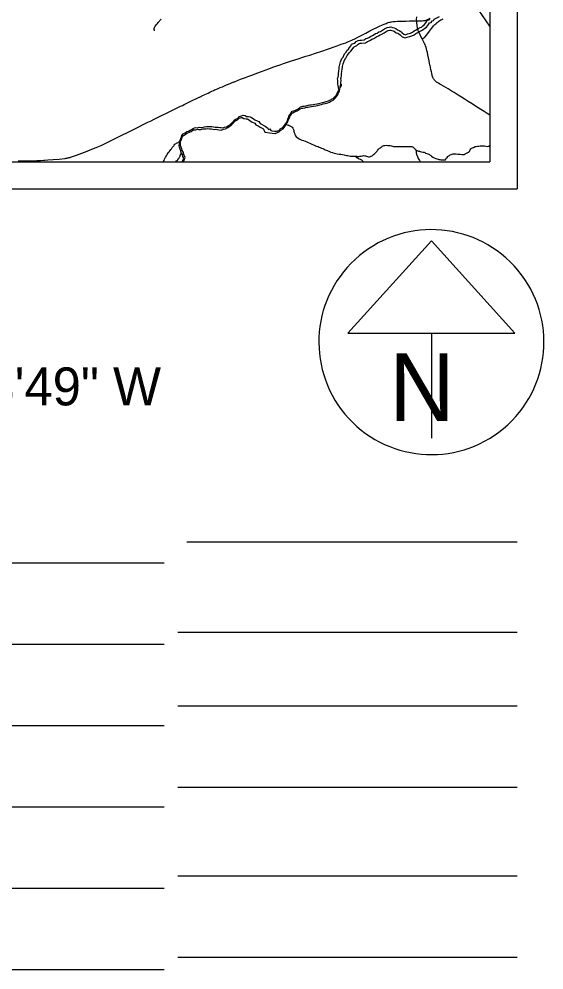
# Model space of a CAD drawing. Extents: x 0 to 34, y -1.2 to 22.
# Drawn here: x 7.165 to 9.099, y 11.12 to 14.627 of the extents above; entities that cross this region are included whole.
import ezdxf

# ---------------------------------------------------------------- set-up
doc = ezdxf.new("R2010")
doc.units = 0
for name, color, linetype in [('GM_X_City_Street', 7, 'Continuous'), ('GM_X_County_Road', 7, 'Continuous'), ('GM_X_Rail_Line', 7, 'Continuous'), ('SH_Cut_Line', 7, 'Continuous'), ('SH_Data', 7, 'Continuous')]:
    doc.layers.add(name, color=color, linetype=linetype)

msp = doc.modelspace()

# ---------------------------------------------------------------- linework, layer by layer
at = {"layer": 'GM_X_City_Street'}
for points in [[(7.6644, 14.5829), (7.6638, 14.5844), (7.6636, 14.5852), (7.6634, 14.586), (7.6632, 14.5867), (7.6631, 14.5875), (7.663, 14.5883), (7.6632, 14.5923), (7.6633, 14.5931), (7.6635, 14.5938), (7.6638, 14.5948), (7.6641, 14.5957), (7.6645, 14.5966), (7.6649, 14.5975), (7.6654, 14.5984), (7.6659, 14.5992), (7.6664, 14.6), (7.6673, 14.6012), (7.6681, 14.6022), (7.6714, 14.6063), (7.6747, 14.6104), (7.678, 14.6145), (7.6882, 14.6268)], [(8.6302, 14.6201), (8.6382, 14.62), (8.6454, 14.6201), (8.651, 14.6204), (8.6559, 14.6208), (8.6603, 14.6215), (8.6628, 14.6219), (8.6651, 14.6226), (8.6676, 14.6235), (8.67, 14.6246), (8.6723, 14.6258), (8.6746, 14.6271)], [(8.6506, 14.5537), (8.6569, 14.557), (8.6593, 14.5587), (8.6615, 14.561), (8.6665, 14.5671), (8.6716, 14.5739), (8.6778, 14.5822), (8.6854, 14.5918), (8.6902, 14.5982), (8.6925, 14.6012), (8.695, 14.604), (8.6975, 14.6067), (8.7002, 14.6094), (8.703, 14.6119), (8.7058, 14.6143), (8.7088, 14.6165), (8.7118, 14.6188), (8.7155, 14.6211), (8.7192, 14.6233), (8.723, 14.6254), (8.7279, 14.628)]]:
    msp.add_lwpolyline(points, dxfattribs=at)
at = {"layer": 'GM_X_County_Road'}
for points in [[(8.6793, 14.4567), (8.678, 14.4635), (8.6762, 14.4731), (8.6741, 14.4838), (8.6718, 14.4948), (8.6698, 14.5036), (8.6682, 14.5103), (8.6669, 14.5155), (8.6649, 14.5223), (8.6626, 14.5284), (8.6609, 14.5328), (8.6591, 14.5369), (8.6567, 14.5419), (8.6506, 14.5537), (8.6461, 14.5627), (8.6413, 14.572), (8.639, 14.577), (8.6375, 14.5805), (8.6357, 14.5859), (8.6346, 14.5899), (8.6333, 14.5952), (8.6324, 14.5999), (8.6317, 14.6043), (8.6307, 14.6122), (8.6304, 14.6158), (8.6302, 14.6201), (8.6301, 14.6249), (8.6304, 14.6344)], [(8.3522, 14.5335), (8.3687, 14.5395), (8.3794, 14.5438), (8.3911, 14.5489), (8.4046, 14.5552), (8.4138, 14.5598), (8.4236, 14.5649), (8.4431, 14.5751), (8.4578, 14.5829), (8.4719, 14.5902), (8.4812, 14.5947), (8.4928, 14.6001), (8.5043, 14.6053), (8.5109, 14.6081), (8.5176, 14.6108), (8.521, 14.6121), (8.5252, 14.6134), (8.53, 14.6147), (8.5337, 14.6156), (8.5378, 14.6164), (8.5438, 14.6171), (8.5511, 14.6177), (8.5597, 14.6183), (8.5734, 14.6188), (8.591, 14.6193), (8.6036, 14.6197), (8.6178, 14.6199), (8.6302, 14.6201)], [(7.1616, 14.1042), (7.1742, 14.1038), (7.2076, 14.104), (7.2191, 14.1042), (7.2302, 14.1046), (7.2443, 14.1052), (7.2558, 14.1058), (7.2593, 14.1059), (7.2703, 14.107), (7.2909, 14.1087), (7.3125, 14.1105), (7.3331, 14.1127), (7.3353, 14.113), (7.3375, 14.1133), (7.3397, 14.1137), (7.3419, 14.1141), (7.3441, 14.1145), (7.3463, 14.115), (7.3484, 14.1155), (7.3506, 14.1161), (7.3527, 14.1167), (7.3548, 14.1173), (7.3761, 14.1248), (7.396, 14.1325), (7.4159, 14.1399), (7.4334, 14.1467), (7.4493, 14.1529), (7.4674, 14.1609), (7.482, 14.1676), (7.4849, 14.1689), (7.502, 14.1771), (7.5215, 14.1868), (7.5387, 14.1954), (7.5723, 14.2122), (7.5896, 14.2208), (7.6063, 14.2292), (7.6226, 14.2374), (7.6398, 14.2459), (7.6514, 14.2519), (7.6625, 14.2575), (7.6754, 14.2639), (7.69, 14.2711), (7.7038, 14.2777), (7.7135, 14.2824), (7.7231, 14.2871), (7.7352, 14.2929), (7.7449, 14.2977), (7.75, 14.3001), (7.7548, 14.3025), (7.7596, 14.3049), (7.7668, 14.3083), (7.7739, 14.3118), (7.7811, 14.3152), (7.8004, 14.3246), (7.8217, 14.3348), (7.8259, 14.3369), (7.8301, 14.339), (7.8343, 14.341), (7.8386, 14.3431), (7.849, 14.3479), (7.8551, 14.3508), (7.8613, 14.3537), (7.8673, 14.3567), (7.8748, 14.3603), (7.8809, 14.3631), (7.8855, 14.3652), (7.8901, 14.3672), (7.898, 14.3706), (7.906, 14.3739), (7.914, 14.3772), (7.9216, 14.3805), (7.9292, 14.3837), (7.9369, 14.3868), (7.9558, 14.3946), (7.9584, 14.3957), (7.9815, 14.4045), (7.9887, 14.4071), (7.999, 14.4112), (8.0121, 14.416), (8.0258, 14.421), (8.0412, 14.4268), (8.0578, 14.433), (8.0724, 14.4384), (8.0853, 14.4433), (8.1006, 14.449), (8.1146, 14.4538), (8.1271, 14.4584), (8.1396, 14.4626), (8.1543, 14.4671), (8.1692, 14.4722), (8.1813, 14.4761), (8.1929, 14.4799), (8.2141, 14.4868), (8.2221, 14.4893), (8.2363, 14.4938), (8.257, 14.5007), (8.2804, 14.5084), (8.3015, 14.5156), (8.334, 14.5271), (8.3522, 14.5335)], [(8.9, 14.2721), (8.8901, 14.2786), (8.8791, 14.2855), (8.867, 14.2931), (8.8573, 14.2992), (8.8469, 14.3059), (8.8343, 14.3139), (8.8201, 14.3229), (8.8053, 14.3323), (8.7955, 14.3386), (8.7832, 14.3463), (8.7684, 14.3556), (8.7613, 14.36), (8.7458, 14.3695), (8.7375, 14.3744), (8.729, 14.3793), (8.7204, 14.3841), (8.7152, 14.3871), (8.7102, 14.3899), (8.7077, 14.3914), (8.7052, 14.3929), (8.7033, 14.3941), (8.7015, 14.3955), (8.6998, 14.397), (8.6983, 14.3986), (8.6959, 14.4016), (8.6943, 14.4038), (8.6928, 14.4061), (8.6915, 14.4085), (8.6902, 14.4114), (8.6889, 14.4152), (8.6876, 14.419), (8.6857, 14.4265), (8.6843, 14.432), (8.6825, 14.4408), (8.681, 14.4482), (8.6795, 14.4557), (8.6793, 14.4567)]]:
    msp.add_lwpolyline(points, dxfattribs=at)
at = {"layer": 'GM_X_Rail_Line'}
msp.add_lwpolyline([(8.9, 14.6003), (8.7511, 14.8178), (8.2939, 15.4393), (8.2013, 15.551), (8.1077, 15.6378), (7.701, 15.9652), (6.7828, 16.6979), (6.6486, 16.8082), (6.5509, 16.8914), (6.4799, 16.9767), (6.4285, 17.0577), (6.3663, 17.169), (6.2482, 17.4528), (6.016, 18.0566), (5.7261, 18.7395), (5.6762, 18.8315), (5.6316, 18.8789), (5.6274, 18.8834)], dxfattribs=at)
at = {"layer": 'SH_Data'}
for p, q in [((9, 21), (9, 14)), ((8.9, 20.9), (8.9, 14.1)), ((2.1, 14.1), (8.9, 14.1)), ((2, 14), (9, 14)), ((8.6845, 13.8091), (8.3769, 13.4678)), ((8.9921, 13.4678), (8.6845, 13.8091)), ((8.3769, 13.4678), (8.9921, 13.4678)), ((8.6845, 13.4678), (8.6845, 13.0811)), ((8.6845, 13.4353), (8.6845, 13.4353)), ((8.6845, 13.4353), (8.6845, 13.4353)), ((7.7827, 12.6985), (9, 12.6985)), ((7.7, 12.6199), (4.4937, 12.6199)), ((9, 12.3639), (7.75, 12.3639)), ((7.7, 12.3199), (3.9895, 12.3199)), ((9, 12.0923), (7.75, 12.0923)), ((7.7, 12.0199), (3.6192, 12.0199)), ((9, 11.7923), (7.75, 11.7923)), ((7.7, 11.7199), (3.3288, 11.7199)), ((9, 11.4655), (7.75, 11.4655)), ((7.7, 11.4199), (4.7452, 11.4199)), ((9, 11.1655), (7.75, 11.1655)), ((7.7, 11.1199), (3.3471, 11.1199))]:
    msp.add_line(p, q, dxfattribs=at)
for points in [[(8.3413, 14.3813), (8.3401, 14.3864), (8.3396, 14.3918), (8.34, 14.4005), (8.3388, 14.4069), (8.3406, 14.4126), (8.3417, 14.4187), (8.3421, 14.4252), (8.3435, 14.4358), (8.3446, 14.443), (8.345, 14.4491), (8.3461, 14.4544), (8.3479, 14.4639), (8.3494, 14.4692), (8.352, 14.4753), (8.3542, 14.481), (8.3587, 14.486), (8.3613, 14.4917), (8.3647, 14.4986), (8.37, 14.505), (8.3733, 14.5104), (8.3786, 14.5153), (8.3831, 14.5214), (8.3888, 14.5287), (8.3906, 14.5336), (8.3974, 14.5359), (8.4023, 14.5382), (8.4076, 14.544), (8.414, 14.547), (8.4208, 14.549), (8.4265, 14.549), (8.4371, 14.5498), (8.4431, 14.5544), (8.4484, 14.5563), (8.4541, 14.5586), (8.4598, 14.5625), (8.4669, 14.5656), (8.4733, 14.5698), (8.479, 14.5728), (8.4843, 14.5748), (8.4903, 14.579), (8.4964, 14.5809), (8.5043, 14.5859), (8.5115, 14.5905), (8.5164, 14.5932), (8.522, 14.5955), (8.5292, 14.597), (8.5353, 14.5974), (8.5417, 14.596), (8.5474, 14.5945), (8.5535, 14.5915), (8.56, 14.5866), (8.5661, 14.5847), (8.5718, 14.5806), (8.5767, 14.5764), (8.5824, 14.5711), (8.5885, 14.5689), (8.5961, 14.5716), (8.6021, 14.5728), (8.6078, 14.5747), (8.6146, 14.5785), (8.6206, 14.5827), (8.6263, 14.5858), (8.6323, 14.5896), (8.638, 14.5927), (8.6433, 14.595), (8.6482, 14.5973), (8.6531, 14.6015), (8.658, 14.605), (8.6644, 14.613), (8.6707, 14.6225), (8.6764, 14.624), (8.6802, 14.6298)], [(8.3484, 14.3751), (8.3513, 14.3882), (8.351, 14.392), (8.3514, 14.4013), (8.3505, 14.4061), (8.3517, 14.4099), (8.3531, 14.4174), (8.3534, 14.4241), (8.3548, 14.4342), (8.3559, 14.4419), (8.3563, 14.4476), (8.3572, 14.4522), (8.359, 14.4613), (8.3601, 14.4655), (8.3625, 14.471), (8.364, 14.4749), (8.3683, 14.4796), (8.3716, 14.4868), (8.3743, 14.4924), (8.3792, 14.4984), (8.3822, 14.5031), (8.3872, 14.5078), (8.3922, 14.5146), (8.3988, 14.5231), (8.3994, 14.5246), (8.4017, 14.5254), (8.4092, 14.5289), (8.4145, 14.5346), (8.4181, 14.5364), (8.4224, 14.5376), (8.427, 14.5376), (8.4413, 14.5387), (8.4486, 14.5443), (8.4525, 14.5457), (8.4595, 14.5486), (8.4652, 14.5525), (8.4723, 14.5555), (8.4792, 14.56), (8.4837, 14.5624), (8.4896, 14.5646), (8.4954, 14.5687), (8.5012, 14.5705), (8.5104, 14.5763), (8.5173, 14.5807), (8.5213, 14.5829), (8.5254, 14.5846), (8.5308, 14.5857), (8.5344, 14.586), (8.539, 14.5849), (8.5434, 14.5838), (8.5475, 14.5818), (8.5547, 14.5763), (8.5609, 14.5744), (8.5648, 14.5716), (8.5692, 14.5679), (8.5764, 14.5613), (8.5884, 14.5568), (8.5991, 14.5606), (8.605, 14.5618), (8.6125, 14.5643), (8.6206, 14.5689), (8.6266, 14.573), (8.632, 14.576), (8.6381, 14.5798), (8.643, 14.5825), (8.648, 14.5847), (8.6544, 14.5877), (8.6601, 14.5925), (8.6658, 14.5966), (8.6735, 14.6063), (8.6778, 14.6126), (8.6835, 14.6142), (8.6874, 14.6201), (8.6926, 14.6218), (8.6952, 14.626), (8.7142, 14.6355)], [(8.0278, 14.2593), (8.0343, 14.2544), (8.0427, 14.2514), (8.0487, 14.2488), (8.053, 14.2419), (8.0587, 14.2393), (8.0663, 14.2344), (8.0716, 14.2322), (8.0765, 14.2284), (8.0819, 14.2246), (8.0842, 14.2197), (8.0894, 14.2213), (8.0921, 14.2156), (8.0978, 14.2149), (8.1058, 14.2134), (8.1141, 14.2127), (8.119, 14.215), (8.1243, 14.2173), (8.1273, 14.2222), (8.1322, 14.2242), (8.1375, 14.2272), (8.1428, 14.2337), (8.1458, 14.2398), (8.1514, 14.2467), (8.1536, 14.2531), (8.1559, 14.2585), (8.1589, 14.2638), (8.1588, 14.2687), (8.1641, 14.2752), (8.1675, 14.2809), (8.1716, 14.2866), (8.1769, 14.2886), (8.1833, 14.2909), (8.1913, 14.2943), (8.1977, 14.2986), (8.2026, 14.3024), (8.2109, 14.3051), (8.2158, 14.3059), (8.2222, 14.307), (8.2306, 14.3094), (8.2362, 14.3098), (8.2412, 14.3106), (8.2483, 14.3114), (8.2548, 14.3129), (8.2635, 14.3141), (8.2688, 14.3153), (8.2778, 14.3176), (8.2835, 14.3188), (8.2896, 14.3207), (8.2964, 14.3226), (8.3058, 14.3254), (8.3107, 14.3273), (8.3183, 14.3319), (8.3232, 14.3338), (8.3285, 14.3395), (8.333, 14.3445), (8.3371, 14.3506), (8.3386, 14.3559), (8.3416, 14.3609), (8.3431, 14.3677), (8.3413, 14.3815)], [(8.3516, 14.3871), (8.3518, 14.381), (8.3484, 14.3751)], [(8.0139, 14.2537), (8.0218, 14.2478), (8.0314, 14.2443), (8.0339, 14.2433), (8.038, 14.2366), (8.0461, 14.2329), (8.0539, 14.2279), (8.0588, 14.2258), (8.0627, 14.2228), (8.0658, 14.2206), (8.071, 14.2095), (8.089, 14.2072), (8.0972, 14.2057), (8.1091, 14.2046), (8.1167, 14.2082), (8.1251, 14.2119), (8.128, 14.2166), (8.1301, 14.2174), (8.138, 14.222), (8.1453, 14.2311), (8.1483, 14.2372), (8.1544, 14.2446), (8.1572, 14.2526), (8.159, 14.257), (8.1632, 14.2644), (8.1632, 14.2683), (8.1664, 14.2722), (8.1699, 14.2782), (8.1717, 14.2807), (8.1737, 14.2814), (8.1805, 14.2839), (8.1896, 14.2878), (8.1972, 14.2928), (8.2009, 14.2957), (8.2065, 14.2975), (8.2107, 14.2982), (8.2177, 14.2995), (8.2254, 14.3017), (8.2305, 14.302), (8.2356, 14.3028), (8.2432, 14.3037), (8.2498, 14.3053), (8.2584, 14.3064), (8.2643, 14.3078), (8.2733, 14.3101), (8.2793, 14.3113), (8.2858, 14.3134), (8.2924, 14.3153), (8.3024, 14.3181), (8.3087, 14.3206), (8.3163, 14.3252), (8.3227, 14.3277), (8.3298, 14.3354), (8.3349, 14.341), (8.3405, 14.3493), (8.3421, 14.3549), (8.3452, 14.3601), (8.3484, 14.3751)], [(7.7669, 14.1), (7.7671, 14.1003), (7.769, 14.106), (7.7716, 14.1132), (7.7681, 14.1193), (7.7673, 14.1272), (7.7627, 14.1333), (7.7612, 14.1409), (7.7585, 14.1465), (7.7558, 14.1537), (7.7554, 14.1587), (7.7557, 14.1651), (7.7561, 14.1708), (7.7556, 14.1757), (7.7594, 14.1822), (7.7609, 14.1875), (7.7631, 14.1925), (7.765, 14.1974), (7.7702, 14.2028), (7.7774, 14.2074), (7.7834, 14.2116), (7.7891, 14.2135), (7.7952, 14.217), (7.8004, 14.2189), (7.8065, 14.2231), (7.8118, 14.2254), (7.8167, 14.2262), (7.822, 14.2258), (7.8292, 14.2282), (7.8349, 14.2271), (7.8402, 14.2271), (7.8481, 14.229), (7.8553, 14.2302), (7.8614, 14.2302), (7.8678, 14.2307), (7.875, 14.2299), (7.8811, 14.2292), (7.8871, 14.2285), (7.8924, 14.2278), (7.8981, 14.2278), (7.9046, 14.2267), (7.9099, 14.2263), (7.9152, 14.2256), (7.9216, 14.2279), (7.9288, 14.2295), (7.9352, 14.2329), (7.9424, 14.2379), (7.948, 14.2421), (7.9533, 14.2478), (7.9601, 14.2555), (7.9653, 14.2582), (7.9706, 14.2605), (7.9778, 14.2673), (7.9842, 14.2693), (7.9906, 14.272), (7.9978, 14.2705), (8.0035, 14.2675), (8.01, 14.2668), (8.016, 14.2664), (8.0214, 14.2638), (8.0278, 14.2593)], [(7.7708, 14.1), (7.7727, 14.1058), (7.777, 14.1178), (7.7721, 14.1263), (7.7712, 14.1351), (7.7663, 14.1416), (7.765, 14.148), (7.7619, 14.1545), (7.7599, 14.1598), (7.7597, 14.1624), (7.76, 14.168), (7.7604, 14.1745), (7.7602, 14.1767), (7.7629, 14.1813), (7.7645, 14.1872), (7.7666, 14.1917), (7.7677, 14.1947), (7.7704, 14.1974), (7.7767, 14.2015), (7.7816, 14.2049), (7.7867, 14.2066), (7.7929, 14.2101), (7.7987, 14.2123), (7.805, 14.2167), (7.8079, 14.2179), (7.8101, 14.2183), (7.8163, 14.2179), (7.8228, 14.22), (7.8267, 14.2192), (7.8345, 14.2193), (7.8433, 14.2214), (7.8492, 14.2224), (7.8547, 14.2224), (7.8605, 14.2228), (7.8667, 14.2222), (7.8726, 14.2215), (7.8786, 14.2207), (7.8846, 14.2199), (7.8901, 14.22), (7.8962, 14.2189), (7.9016, 14.2186), (7.9093, 14.2175), (7.9177, 14.2205), (7.9257, 14.2222), (7.9341, 14.2268), (7.9419, 14.2322), (7.9486, 14.2372), (7.9547, 14.2438), (7.9601, 14.2498), (7.9631, 14.2514), (7.97, 14.2544), (7.9766, 14.2608), (7.981, 14.2621), (7.9847, 14.2637), (7.9869, 14.2632), (7.9931, 14.26), (8.002, 14.259), (8.006, 14.2587), (8.0085, 14.2575), (8.0143, 14.2535)], [(8.1487, 14.2376), (8.1606, 14.2338), (8.1572, 14.2349), (8.1606, 14.2338), (8.1633, 14.2331), (8.1652, 14.232), (8.1671, 14.2305), (8.1694, 14.2294), (8.1714, 14.2275), (8.1733, 14.2245), (8.1752, 14.2219), (8.1768, 14.2196), (8.1776, 14.2162), (8.178, 14.2124), (8.1788, 14.2086), (8.1796, 14.2056), (8.1808, 14.2029), (8.1816, 14.2003), (8.1827, 14.198), (8.1839, 14.1961), (8.1859, 14.1927), (8.1889, 14.1905), (8.1973, 14.1845), (8.2015, 14.1823), (8.2073, 14.1801), (8.2134, 14.1782), (8.2195, 14.1764), (8.2252, 14.1742), (8.2309, 14.1716), (8.2366, 14.1686), (8.2439, 14.1657), (8.2496, 14.1631), (8.2553, 14.1601), (8.2603, 14.1583), (8.2645, 14.1572), (8.2675, 14.1561), (8.2706, 14.1546), (8.2744, 14.1528), (8.279, 14.1505), (8.2843, 14.1487), (8.2893, 14.1473), (8.2931, 14.1446), (8.3, 14.1421), (8.3065, 14.1391), (8.3133, 14.1361), (8.3202, 14.134), (8.3263, 14.1321), (8.332, 14.1307), (8.3377, 14.13), (8.3445, 14.1289), (8.3506, 14.1279), (8.3571, 14.1268), (8.3632, 14.1258), (8.3712, 14.124), (8.3769, 14.1229), (8.3818, 14.1218), (8.386, 14.1211), (8.3902, 14.1204), (8.3951, 14.1205), (8.4001, 14.1205), (8.4054, 14.1206), (8.4092, 14.1206), (8.4115, 14.1203), (8.4137, 14.1199), (8.4168, 14.12), (8.4202, 14.1204), (8.4228, 14.1208), (8.4259, 14.1212), (8.43, 14.1224), (8.4346, 14.1229), (8.4387, 14.1225), (8.4418, 14.1222), (8.4528, 14.1185), (8.4563, 14.1186), (8.46, 14.1194), (8.4627, 14.1209), (8.4657, 14.1225), (8.4683, 14.1244), (8.4713, 14.1268), (8.4751, 14.1298), (8.4785, 14.1329), (8.4815, 14.136), (8.4841, 14.1391), (8.4863, 14.1422), (8.4893, 14.1464), (8.493, 14.1502), (8.4964, 14.1522), (8.499, 14.1545), (8.5013, 14.156), (8.5036, 14.1576), (8.5062, 14.1591), (8.5096, 14.1599), (8.5134, 14.1608), (8.5187, 14.1612), (8.5236, 14.1609), (8.5282, 14.1602), (8.5328, 14.1599), (8.5373, 14.1588), (8.5408, 14.1577), (8.5449, 14.157), (8.5487, 14.1563)], [(7.6972, 14.1), (7.6975, 14.1009), (7.699, 14.1051), (7.7012, 14.1105), (7.7049, 14.1174), (7.7078, 14.1227), (7.7108, 14.1277), (7.7145, 14.1331), (7.7183, 14.1373), (7.7213, 14.1419), (7.7242, 14.1457), (7.7269, 14.1484), (7.7295, 14.153), (7.7324, 14.1565), (7.7347, 14.1596), (7.7369, 14.1619), (7.7392, 14.1653), (7.7557, 14.1756)], [(8.5487, 14.1563), (8.5525, 14.1563), (8.5582, 14.1564), (8.5647, 14.1565), (8.5715, 14.1562), (8.5768, 14.1562), (8.581, 14.1567), (8.5848, 14.1563), (8.5886, 14.1568), (8.5946, 14.1569), (8.5996, 14.1569), (8.6038, 14.157), (8.6079, 14.157), (8.6121, 14.1563), (8.6152, 14.1552), (8.6178, 14.1537), (8.6198, 14.1519), (8.6221, 14.1496), (8.6244, 14.147), (8.6267, 14.1447), (8.6301, 14.1421), (8.632, 14.1414), (8.6374, 14.1399), (8.64, 14.1396), (8.6435, 14.1385), (8.648, 14.137), (8.653, 14.1363), (8.6572, 14.1352), (8.6598, 14.1341), (8.6629, 14.1322), (8.6682, 14.1308), (8.6717, 14.1297), (8.6751, 14.1282), (8.6778, 14.1267), (8.6801, 14.1252), (8.6824, 14.123), (8.6854, 14.1207), (8.6897, 14.1178), (8.695, 14.1148), (8.7003, 14.1126), (8.7049, 14.1115), (8.7095, 14.11), (8.7122, 14.1093), (8.7156, 14.1086), (8.7198, 14.1079), (8.7239, 14.1075), (8.7274, 14.1076), (8.7304, 14.1076), (8.7338, 14.1077), (8.7365, 14.1081), (8.739, 14.1131), (8.7424, 14.1165), (8.7447, 14.1192), (8.7465, 14.1204), (8.7484, 14.1223), (8.751, 14.1239), (8.7541, 14.1258), (8.7575, 14.127), (8.7609, 14.1285), (8.765, 14.1297), (8.7673, 14.1298), (8.7692, 14.1298), (8.7719, 14.1295), (8.776, 14.1291), (8.7825, 14.1284), (8.7901, 14.1278), (8.7965, 14.1275), (8.8049, 14.1272), (8.8083, 14.1295), (8.8143, 14.1319), (8.8188, 14.1342), (8.8222, 14.1358), (8.8241, 14.1377), (8.8256, 14.1396), (8.8263, 14.1416), (8.8278, 14.1446), (8.8297, 14.1477), (8.8327, 14.15), (8.8361, 14.1519), (8.8395, 14.1535), (8.8455, 14.1563), (8.8497, 14.1571), (8.8538, 14.1579), (8.8588, 14.1583), (8.8641, 14.1588), (8.8694, 14.1588), (8.8743, 14.1589), (8.8796, 14.1586), (8.8853, 14.1579), (8.8903, 14.1572), (8.8941, 14.1573), (8.8963, 14.1584), (8.8993, 14.16), (8.9, 14.161)], [(8.6273, 14.1443), (8.6296, 14.1257), (8.6315, 14.1235), (8.6331, 14.1197), (8.6343, 14.1167), (8.6362, 14.1125), (8.6382, 14.1087), (8.6405, 14.1053), (8.6424, 14.1031), (8.6437, 14.1)], [(7.742, 14.1), (7.7449, 14.1034), (7.7483, 14.1061), (7.7498, 14.108), (7.7516, 14.1107), (7.7535, 14.113), (7.7546, 14.1149), (7.7557, 14.1169), (7.7568, 14.1192), (7.758, 14.1211), (7.7587, 14.1234), (7.7605, 14.1276), (7.7631, 14.1328)], [(8.4065, 14.1206), (8.4065, 14.1191), (8.4092, 14.1161), (8.4142, 14.1131), (8.4188, 14.1109), (8.4222, 14.1094), (8.4249, 14.1083), (8.4268, 14.1076), (8.4295, 14.1049), (8.4318, 14.1031), (8.4333, 14.1008), (8.434, 14.1)]]:
    msp.add_lwpolyline(points, dxfattribs=at)
msp.add_arc((8.6845, 13.4353), 0.4148, 129.7798, 129.7633, dxfattribs=at)

# ---------------------------------------------------------------- texts
at = {"layer": 'SH_Cut_Line'}
msp.add_text('LATITUDE:    41°24\'26" N    LONGITUDE:    81°38\'49" W', height=0.14, dxfattribs=at).set_placement((2.9431, 13.202))
at = {"layer": 'SH_Data'}
msp.add_text('N', height=0.25, dxfattribs=at).set_placement((8.5292, 13.144))

doc.saveas('drawing.dxf')
